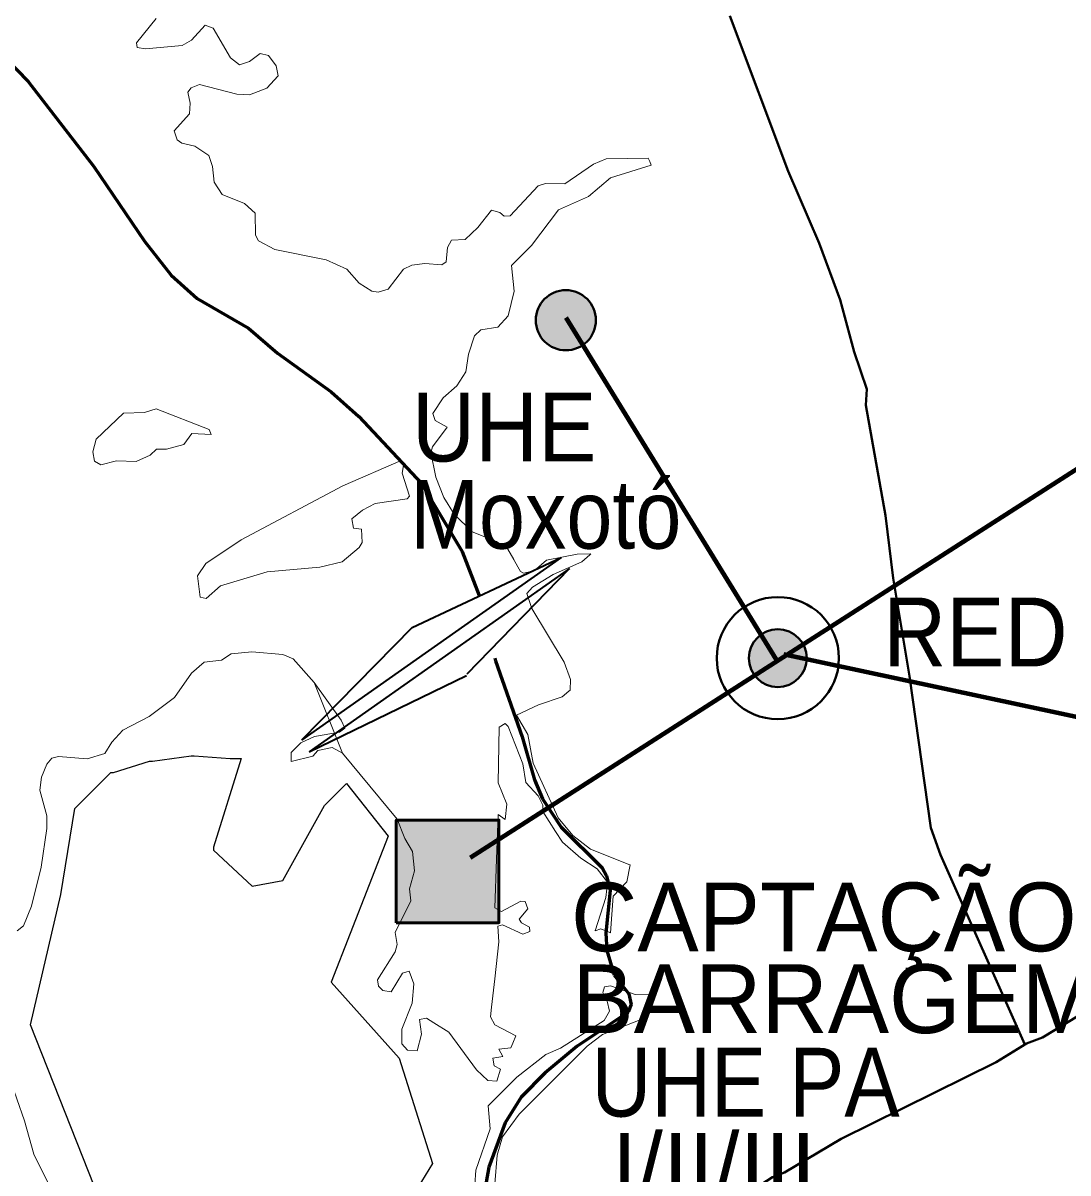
# Model space of a CAD drawing. Extents: x 553962 to 842807, y 8883888 to 9032388.
# Drawn here: x 584109 to 591710, y 8960294 to 8968659 of the extents above; entities that cross this region are included whole.
import ezdxf
from ezdxf.enums import TextEntityAlignment as Align

# ---------------------------------------------------------------- set-up
doc = ezdxf.new("R2010")
doc.units = 0
doc.header["$LTSCALE"] = 200
doc.linetypes.add('LONG_DASH_SHORT_DASH', pattern=[9.9, 6, -1.2, 1.5, -1.2])
for name, color, linetype, lineweight in [('12', 7, 'Continuous', 25), ('21', 7, 'Continuous', 25), ('25', 7, 'Continuous', 13), ('28', 7, 'Continuous', 40), ('41', 7, 'Continuous', 40), ('7', 7, 'LONG_DASH_SHORT_DASH', 60)]:
    doc.layers.add(name, color=color, linetype=linetype, lineweight=lineweight)

msp = doc.modelspace()

# ---------------------------------------------------------------- hatches: boundary and pattern name
at = {"layer": '28'}
for points in [[(589809.6, 8964039.6, 1), (589388.8, 8964039.6, 1)], [(586823.5, 8962114.4), (587570.9, 8962114.4), (587570.9, 8962861.8), (586823.5, 8962861.8)]]:
    msp.add_hatch(color=256, dxfattribs=at).paths.add_polyline_path(points)
at = {"layer": '41'}
msp.add_hatch(color=256, dxfattribs=at).paths.add_polyline_path([(588276.2, 8966497.4, 1), (587838.6, 8966497.4, 1)])

# ---------------------------------------------------------------- linework, layer by layer
at = {"layer": '12', "lineweight": 40}
for points in [[(589251, 8968710.7), (589674.6, 8967582.3), (589899.5, 8967058.9), (590052.2, 8966645.4), (590154.6, 8966267.7), (590247.4, 8965995.5), (590238.8, 8965878.8), (590381.4, 8965077.2), (590437.7, 8964620.9), (590556.9, 8963909.5), (590712.3, 8962804.7), (590781.8, 8962609.4), (591396.4, 8961227.9)], [(587134, 8956453.8), (587843.6, 8957685.7), (587923.7, 8957988.5), (588169.9, 8958625.1), (588237, 8958904.7), (588304.1, 8959099.5), (588468, 8959448.9), (588578.9, 8959635.8), (588673.7, 8959750.1), (588777.5, 8959843.1), (589203.6, 8960089.7), (589393.4, 8960175.8), (589428.5, 8960178.5), (589560.1, 8960264.6), (589648.9, 8960297.2), (590059.4, 8960543.5), (591188.1, 8961101.4), (591408.7, 8961235.4), (591525.3, 8961280.9), (591868.7, 8961488.1), (592154.1, 8961587.2), (592311.1, 8961655)]]:
    msp.add_lwpolyline(points, dxfattribs=at)
at = {"layer": '21'}
msp.add_lwpolyline([(584626.8, 8960201.4), (584162.8, 8961372.1), (584384.7, 8962320.7), (584485.6, 8962946.4), (584747.9, 8963208.8), (584768.1, 8963208.8), (585030.4, 8963289.5), (585050.6, 8963289.5), (585333, 8963329.9), (585353.2, 8963329.9), (585615.5, 8963309.7), (585655.9, 8963309.7), (585676, 8963309.7), (585696.2, 8963309.7), (585494.5, 8962663.8), (585494.5, 8962643.7), (585776.9, 8962381.3), (585998.9, 8962421.6), (586301.5, 8962966.6), (586463, 8963128.1), (586765.6, 8962744.6), (586351.3, 8961682.2), (586846.3, 8961129.9), (587088.5, 8960362.9), (586927, 8960100.5)], dxfattribs=at)
at = {"layer": '25', "lineweight": 35}
for p, q in [((588022.6, 8964770.6), (586135.6, 8963442.6)), ((586940.7, 8964263.4), (588022.6, 8964770.6)), ((588084.7, 8964692), (586189.9, 8963358.5)), ((587339.3, 8963925.5), (588084.7, 8964692)), ((586940.7, 8964263.4), (586135.6, 8963442.6)), ((586189.9, 8963358.5), (587335.7, 8963913.8))]:
    msp.add_line(p, q, dxfattribs=at)
at = {"layer": '25'}
for points in [[(585077.6, 8968692.1), (584933.7, 8968514.1), (584939.8, 8968481.6), (585001.2, 8968471), (585266.9, 8968496.5), (585333.9, 8968534), (585434.5, 8968644.9), (585434.5, 8968644.9), (585492.3, 8968621), (585617.4, 8968405), (585683.3, 8968356.3), (585757.2, 8968379.6), (585833.8, 8968436.8), (585893.9, 8968423.6), (585950.2, 8968348.5), (585965.4, 8968274.1), (585883, 8968184.3), (585757.4, 8968137.5), (585664, 8968141.7), (585392.1, 8968211.7), (585332.8, 8968188.5), (585307.1, 8968156.3), (585324, 8968076.1), (585319.8, 8967999.4)], [(585077.6, 8968692.1), (584933.7, 8968514.1), (584939.8, 8968481.6), (585001.2, 8968471), (585266.9, 8968496.5), (585333.9, 8968534), (585434.5, 8968644.9), (585434.5, 8968644.9), (585492.3, 8968621), (585617.4, 8968405), (585683.3, 8968356.3), (585757.2, 8968379.6), (585833.8, 8968436.8), (585893.9, 8968423.6), (585950.2, 8968348.5), (585965.4, 8968274.1), (585883, 8968184.3), (585757.4, 8968137.5), (585664, 8968141.7), (585392.1, 8968211.7), (585332.8, 8968188.5), (585307.1, 8968156.3), (585324, 8968076.1), (585319.8, 8967999.4)], [(585319.8, 8967999.4), (585209.4, 8967874), (585230.7, 8967810.4), (585264.6, 8967784.9), (585358.3, 8967763.5), (585460, 8967695.5), (585487.7, 8967616.8), (585500.5, 8967502.3), (585557.8, 8967413.1), (585721.3, 8967347.2), (585797.8, 8967276.9), (585799.9, 8967116.4), (585821.7, 8967075), (585940.4, 8967011.6), (586314, 8966937.2), (586464.8, 8966869.3), (586554.2, 8966767.2), (586645.4, 8966710), (586692.1, 8966701.5), (586766.2, 8966722.7), (586877, 8966869.2), (586938.3, 8966898.9), (587031.7, 8966909.6), (587155.3, 8966899.2), (587187, 8966922.6), (587195.6, 8967026.5), (587225.2, 8967079.4), (587325, 8967083.9), (587416.4, 8967171), (587516.5, 8967298.4), (587577.2, 8967281.7), (587609.8, 8967253.9), (587652.2, 8967256), (587856.2, 8967474.6), (587908.7, 8967491.8), (588049.3, 8967489.5), (588259.2, 8967631.5), (588349.7, 8967670.3), (588657.3, 8967677.5), (588667.8, 8967651.8)], [(585319.8, 8967999.4), (585209.4, 8967874), (585230.7, 8967810.4), (585264.6, 8967784.9), (585358.3, 8967763.5), (585460, 8967695.5), (585487.7, 8967616.8), (585500.5, 8967502.3), (585557.8, 8967413.1), (585721.3, 8967347.2), (585797.8, 8967276.9), (585799.9, 8967116.4), (585821.7, 8967075), (585940.4, 8967011.6), (586314, 8966937.2), (586464.8, 8966869.3), (586554.2, 8966767.2), (586645.4, 8966710), (586692.1, 8966701.5), (586766.2, 8966722.7), (586877, 8966869.2), (586938.3, 8966898.9), (587031.7, 8966909.6), (587155.3, 8966899.2), (587187, 8966922.6), (587195.6, 8967026.5), (587225.2, 8967079.4), (587325, 8967083.9), (587416.4, 8967171), (587516.5, 8967298.4), (587577.2, 8967281.7), (587609.8, 8967253.9), (587652.2, 8967256), (587856.2, 8967474.6), (587908.7, 8967491.8), (588049.3, 8967489.5), (588259.2, 8967631.5), (588349.7, 8967670.3), (588657.3, 8967677.5), (588667.8, 8967651.8)], [(588667.8, 8967651.8), (588678.2, 8967626.5), (588381.1, 8967532.1), (588221.7, 8967398.4), (588005.1, 8967300.6), (587807.3, 8967041.3), (587663.1, 8966894.9), (587682, 8966707.8), (587637.4, 8966529.4), (587563.2, 8966446.7), (587438, 8966427.4), (587392.7, 8966384.2), (587348.6, 8966249.6), (587329.2, 8966121.3), (587265.6, 8966019.6), (587165.8, 8965932.5), (587089.5, 8965818), (587106.5, 8965769), (587193.3, 8965719.9), (587087.2, 8965577.5), (587074.5, 8965534.6), (587110.7, 8965356.6), (587170.4, 8965207.5), (587244.3, 8965087.2), (587376.1, 8964957.5), (587554.3, 8964887.4), (587635.2, 8964832.1), (587726.7, 8964670.8), (587750.6, 8964658), (587826.4, 8964675), (587917.9, 8964751.3), (588138.8, 8964796.3), (588239.8, 8964798.6), (588239.8, 8964798.6), (588231, 8964790.9)], [(588667.8, 8967651.8), (588678.2, 8967626.5), (588381.1, 8967532.1), (588221.7, 8967398.4), (588005.1, 8967300.6), (587807.3, 8967041.3), (587663.1, 8966894.9), (587682, 8966707.8), (587637.4, 8966529.4), (587563.2, 8966446.7), (587438, 8966427.4), (587392.7, 8966384.2), (587348.6, 8966249.6), (587329.2, 8966121.3), (587265.6, 8966019.6), (587165.8, 8965932.5), (587089.5, 8965818), (587106.5, 8965769), (587193.3, 8965719.9), (587087.2, 8965577.5), (587074.5, 8965534.6), (587110.7, 8965356.6), (587170.4, 8965207.5), (587244.3, 8965087.2), (587376.1, 8964957.5), (587554.3, 8964887.4), (587635.2, 8964832.1), (587678.5, 8964757.6)], [(588231, 8964790.9), (588174.2, 8964740.5), (587964.7, 8964647.4), (587813.9, 8964556), (587773.6, 8964509.6), (587809.5, 8964400.9), (588045.3, 8964009.8), (588090.5, 8963883.4), (588087.9, 8963805.8), (588079.5, 8963798.7)], [(587773.6, 8964509.6), (587809.5, 8964400.9), (588045.3, 8964009.8), (588090.5, 8963883.4), (588087.9, 8963805.8), (588079.5, 8963798.7)], [(587098.4, 8961386.8), (587045, 8961420.4), (586993.8, 8961411.8), (587008.6, 8961303.5), (586976.2, 8961182.7), (586906.7, 8961189.1), (586864.3, 8961233.5), (586864.2, 8961341.7), (586938.6, 8961529.2), (586953.1, 8961669.7), (586916.8, 8961762.6), (586868.3, 8961747.5), (586787.2, 8961611.7), (586725.9, 8961622.5), (586694.3, 8961654.3), (586687.9, 8961700.7), (586815.2, 8961902.8), (586830.2, 8961956.5), (586815.4, 8962043.2), (586930, 8962273.3), (586921.5, 8962361.5), (586957.6, 8962493.3), (586943, 8962632.7), (586885.4, 8962727), (586830, 8962867.4), (586432.9, 8963349.4), (586358.6, 8963389.7), (586254.6, 8963368.5), (586216.2, 8963326.1), (586059.1, 8963288.1), (586058.9, 8963353.2), (586131.1, 8963423.6), (586229.2, 8963469.6), (586410.8, 8963500), (586449.8, 8963530), (586424.4, 8963587.3), (586226.9, 8963861.3), (586073.9, 8964035.5), (585999.3, 8964065.2), (585774.7, 8964084.4), (585623.6, 8964071.6), (585553.5, 8964025), (585426.1, 8964010), (585334.9, 8963929.5), (585211.3, 8963752.8), (585026.9, 8963615.1), (584835.5, 8963515.1), (584755, 8963428.2), (584703.5, 8963345.2), (584575.7, 8963306.9), (584575.7, 8963306.9), (584367.9, 8963323.8), (584319.4, 8963311.1), (584283.8, 8963267.3), (584244.9, 8963172.8), (584232.2, 8963079.6), (584283.2, 8962892.7), (584283.2, 8962799.2), (584240.7, 8962518.8), (584172.1, 8962236.3), (584113.2, 8962091.9), (584066.4, 8962055.5)], [(587098.4, 8961386.8), (587045, 8961420.4), (586993.8, 8961411.8), (587008.6, 8961303.5), (586976.2, 8961182.7), (586906.7, 8961189.1), (586864.3, 8961233.5), (586864.2, 8961341.7), (586938.6, 8961529.2), (586953.1, 8961669.7), (586916.8, 8961762.6), (586868.3, 8961747.5), (586787.2, 8961611.7), (586725.9, 8961622.5), (586694.3, 8961654.3), (586687.9, 8961700.7), (586815.2, 8961902.8), (586830.2, 8961956.5), (586815.4, 8962043.2), (586930, 8962273.3), (586921.5, 8962361.5), (586957.6, 8962493.3), (586943, 8962632.7), (586885.4, 8962727), (586830, 8962867.4), (586432.9, 8963349.4), (586226.9, 8963861.3), (586073.9, 8964035.5), (585999.3, 8964065.2), (585774.7, 8964084.4), (585623.6, 8964071.6), (585553.5, 8964025), (585426.1, 8964010), (585334.9, 8963929.5), (585211.3, 8963752.8), (585026.9, 8963615.1), (584835.5, 8963515.1), (584755, 8963428.2), (584703.5, 8963345.2), (584575.7, 8963306.9), (584575.7, 8963306.9), (584367.9, 8963323.8), (584319.4, 8963311.1), (584283.8, 8963267.3), (584244.9, 8963172.8), (584232.2, 8963079.6), (584283.2, 8962892.7), (584283.2, 8962799.2), (584240.7, 8962518.8), (584172.1, 8962236.3), (584113.2, 8962091.9), (584066.4, 8962055.5)], [(588079.5, 8963798.7), (588030.2, 8963757.2), (587858.5, 8963700), (587699.1, 8963625.3), (587781.9, 8963483), (587820, 8963275.3), (588002, 8962877.1), (588002, 8962877.1), (588108.8, 8962750.5), (588236.2, 8962650.7), (588523, 8962536.8)], [(588079.5, 8963798.7), (588030.2, 8963757.2), (587858.5, 8963700), (587699.1, 8963625.3), (587781.9, 8963483), (587820, 8963275.3), (588002, 8962877.1), (588002, 8962877.1), (588108.8, 8962750.5), (588236.2, 8962650.7), (588523, 8962536.8)], [(587982.8, 8962779.3), (587890.3, 8962924.4), (587890.1, 8962969.1), (587856.3, 8963036.9), (587766.9, 8963135.1), (587743.6, 8963270.8), (587637.1, 8963543.2), (587617, 8963563.8), (587571.7, 8963538.4), (587565.1, 8963131.3), (587628.8, 8962977.9), (587616.1, 8962866.9), (587565.4, 8962902.1), (587554.1, 8962576.4)], [(587982.8, 8962779.3), (587890.3, 8962924.4), (587890.1, 8962969.1), (587856.3, 8963036.9), (587766.9, 8963135.1), (587743.6, 8963270.8), (587637.1, 8963543.2), (587617, 8963563.8), (587571.7, 8963538.4), (587565.1, 8963131.3), (587628.8, 8962977.9), (587616.1, 8962866.9), (587565.4, 8962902.1), (587554.1, 8962576.4)], [(588354.5, 8962361.1), (588359.4, 8962408.8), (588285.5, 8962505.9), (588167, 8962584.2), (588032.3, 8962701.8), (587982.8, 8962779.3)], [(588354.5, 8962361.1), (588359.4, 8962408.8), (588285.5, 8962505.9), (588167, 8962584.2), (588032.3, 8962701.8), (587982.8, 8962779.3)], [(587554.1, 8962576.4), (587541.8, 8962223.9), (587588.7, 8962196), (587730.7, 8962272.2), (587762.7, 8962269), (587781.7, 8962215.1)], [(587554.1, 8962576.4), (587541.8, 8962223.9), (587588.7, 8962196), (587730.7, 8962272.2), (587762.7, 8962269), (587781.7, 8962215.1)], [(588523, 8962536.8), (588524.4, 8962536.2), (588501.9, 8962412.8), (588402.2, 8962308.3), (588381.1, 8962040.8), (588376.4, 8962042.8)], [(588523, 8962536.8), (588524.4, 8962536.2), (588501.9, 8962412.8), (588402.2, 8962308.3), (588381.1, 8962040.8), (588376.4, 8962042.8)], [(588271.6, 8962055.8), (588270.1, 8962055.2), (588348.1, 8962299.3), (588354.5, 8962361.1)], [(588271.6, 8962055.8), (588270.1, 8962055.2), (588348.1, 8962299.3), (588354.5, 8962361.1)], [(587781.7, 8962215.1), (587781.7, 8962215.1), (587718.2, 8962140.9), (587735, 8962113.3), (587792.4, 8962083.3), (587794.6, 8962050), (587745.5, 8962032.4), (587597.2, 8962100.2), (587563.1, 8962089.5), (587569.5, 8961975.7), (587540.2, 8961707.3), (587517.7, 8961501.6)], [(587781.7, 8962215.1), (587781.7, 8962215.1), (587718.2, 8962140.9), (587735, 8962113.3), (587792.4, 8962083.3), (587794.6, 8962050), (587745.5, 8962032.4), (587597.2, 8962100.2), (587563.1, 8962089.5), (587569.5, 8961975.7), (587540.2, 8961707.3), (587517.7, 8961501.6)], [(588376.4, 8962042.8), (588311.2, 8962069.4), (588271.6, 8962055.8), (588271.7, 8962060.3), (588271.6, 8962055.8)], [(588376.4, 8962042.8), (588311.2, 8962069.4), (588271.6, 8962055.8), (588271.7, 8962060.3), (588271.6, 8962055.8)], [(587541.6, 8960215), (587558.8, 8960425), (587596.7, 8960558.6), (587717.4, 8960723.2), (588213.5, 8961217.2), (588323.7, 8961300.9), (588630.6, 8961421.7), (588681.9, 8961493.8), (588689.2, 8961575.7), (588675.2, 8961590.7), (588561, 8961592.8), (588381.1, 8961656.2), (588338.6, 8961648.6), (588325.4, 8961606.6), (588359, 8961544.8), (588373.9, 8961471.3), (588335.7, 8961403.9), (588018, 8961201.6), (587911.6, 8961156.7), (587701, 8960992.4), (587493.3, 8960783.2), (587506.9, 8960616.2), (587403.7, 8960314.5), (587373.8, 8959887.7)], [(587517.7, 8961501.6), (587510, 8961431.2), (587539.9, 8961371.6), (587692.7, 8961292.6), (587670.8, 8961239.2)], [(587517.7, 8961501.6), (587510, 8961431.2), (587539.9, 8961371.6), (587692.7, 8961292.6), (587670.8, 8961239.2)], [(587670.8, 8961239.2), (587656.4, 8961204.1), (587570.6, 8961194.6), (587599.2, 8961141.8), (587527.1, 8961129.4), (587535.4, 8961074.6), (587582.5, 8961050.1), (587556.1, 8960961.2), (587491.1, 8960968.1), (587408.1, 8961044.4), (587205.3, 8961319.5), (587098.4, 8961386.8)], [(587670.8, 8961239.2), (587656.4, 8961204.1), (587570.6, 8961194.6), (587599.2, 8961141.8), (587527.1, 8961129.4), (587535.4, 8961074.6), (587582.5, 8961050.1), (587556.1, 8960961.2), (587491.1, 8960968.1), (587408.1, 8961044.4), (587205.3, 8961319.5), (587098.4, 8961386.8)], [(584009.2, 8960993.4), (584121.2, 8960674.7), (584187.7, 8960432.6), (584325.6, 8960152.6)], [(584009.2, 8960993.4), (584121.2, 8960674.7), (584187.7, 8960432.6), (584325.6, 8960152.6)]]:
    msp.add_lwpolyline(points, dxfattribs=at)
for points in [[(585077.7, 8965854), (584992.7, 8965826.3), (584839.9, 8965820.3), (584642.3, 8965632.9), (584616.8, 8965540.1), (584629.5, 8965471.6), (584675.9, 8965446), (584789, 8965475.7), (584933.4, 8965469.6), (585035.3, 8965516.3), (585079.8, 8965558.5), (585154.1, 8965558.7), (585279.1, 8965592.6), (585337.4, 8965673.5), (585478.9, 8965666.9), (585463.8, 8965703.2)], [(585077.7, 8965854), (584992.7, 8965826.3), (584839.9, 8965820.3), (584642.3, 8965632.9), (584616.8, 8965540.1), (584629.5, 8965471.6), (584675.9, 8965446), (584789, 8965475.7), (584933.4, 8965469.6), (585035.3, 8965516.3), (585079.8, 8965558.5), (585154.1, 8965558.7), (585279.1, 8965592.6), (585337.4, 8965673.5), (585478.9, 8965666.9), (585463.8, 8965703.2)], [(585439, 8964728.2), (585379.4, 8964639), (585398.5, 8964484), (585440.9, 8964473.3), (585545, 8964564.5), (585884.6, 8964666.3), (586267.5, 8964700.5), (586430.8, 8964740.8), (586553.9, 8964845), (586575.2, 8964881), (586570.7, 8964976.5), (586513.6, 8964985.3), (586501.3, 8965053.3), (586579.7, 8965116.9), (586670.6, 8965163.4), (586903.9, 8965197.4), (586919.2, 8965218.6), (586866.7, 8965384.8), (586876.8, 8965441.6), (586860, 8965477.5), (586435.1, 8965293.1), (585696.3, 8964900.4)], [(585439, 8964728.2), (585379.4, 8964639), (585398.5, 8964484), (585440.9, 8964473.3), (585545, 8964564.5), (585884.6, 8964666.3), (586267.5, 8964700.5), (586430.8, 8964740.8), (586553.9, 8964845), (586575.2, 8964881), (586570.7, 8964976.5), (586513.6, 8964985.3), (586501.3, 8965053.3), (586579.7, 8965116.9), (586670.6, 8965163.4), (586903.9, 8965197.4), (586919.2, 8965218.6), (586866.7, 8965384.8), (586876.8, 8965441.6), (586860, 8965477.5), (586435.1, 8965293.1), (585696.3, 8964900.4)]]:
    msp.add_lwpolyline(points, close=True, dxfattribs=at)
at = {"layer": '28', "lineweight": 80}
for p, q in [((587364.8, 8962590.1), (595824.3, 8968009.9)), ((588057.4, 8966518), (589588, 8964029.1)), ((596799.2, 8962536.5), (589643, 8964065.2))]:
    msp.add_line(p, q, dxfattribs=at)
at = {"layer": '28', "lineweight": 53}
msp.add_lwpolyline([(586823.5, 8962114.4), (587570.9, 8962114.4), (587570.9, 8962861.8), (586823.5, 8962861.8)], close=True, dxfattribs=at)
at = {"layer": '28'}
for radius in [444.4, 210.4]:
    msp.add_circle((589599.2, 8964039.6), radius, dxfattribs=at)
at = {"layer": '41'}
msp.add_circle((588057.4, 8966497.4), 218.8, dxfattribs=at)
at = {"layer": '7'}
for points in [[(583174.4, 8969966), (583327.9, 8969505.4), (583474.7, 8969160.4), (583725.5, 8968684.8), (583883.2, 8968539.9), (583982.9, 8968403.5), (584146.9, 8968235.1), (584624.8, 8967616.6), (584992.2, 8967072.1), (585186.8, 8966825.7), (585377.2, 8966655.9), (585748.8, 8966438.6), (585960.5, 8966257.3), (586351.6, 8965976.8), (586551, 8965796.4), (587006.6, 8965310.9), (587303.1, 8964815.2), (587426.7, 8964495.3)], [(587540.9, 8964040.5), (587545.5, 8964019), (587739.9, 8963466), (587828.5, 8963155), (587886.8, 8963016.8), (588023, 8962809.1), (588321.3, 8962515.1), (588353.7, 8962454.8), (588379.7, 8962350), (588349.5, 8962039.7), (588356.1, 8961913.4), (588409.9, 8961732.7), (588515.9, 8961598.5), (588533, 8961520.2), (588511.4, 8961464.3), (588140, 8961216), (587908.2, 8961023.1), (587733.4, 8960846.2), (587616.5, 8960660), (587498.3, 8960337.4), (587362.2, 8959603), (587314, 8959147.2), (587303.2, 8958935.8), (587310.7, 8958873)]]:
    msp.add_lwpolyline(points, dxfattribs=at)

# ---------------------------------------------------------------- texts
at = {"layer": '28'}
for s, width, p in [('UHE', 0.95, (587609.2, 8965470.1)), ('Moxotó', 0.9, (587911.1, 8964836.1)), ('UHE PA', 0.9, (589364.5, 8960705))]:
    msp.add_text(s, height=500, dxfattribs=dict(at, width=width)).set_placement(p, align=Align.CENTER)
at = {"layer": '28', "width": 0.95}
msp.add_text('RED', height=500, dxfattribs=at).set_placement((590365.9, 8963979.7))
at = {"layer": '28'}
for s, p in [('CAPTAÇÃO FLUTUANTE', (588094.9, 8961907)), ('BARRAGEM LESTE', (588105, 8961312))]:
    msp.add_text(s, height=500, dxfattribs=at).set_placement(p)
msp.add_text('I/II/III', height=500, dxfattribs=at).set_placement((589134.4, 8960086.2), align=Align.CENTER)

doc.saveas('drawing.dxf')
